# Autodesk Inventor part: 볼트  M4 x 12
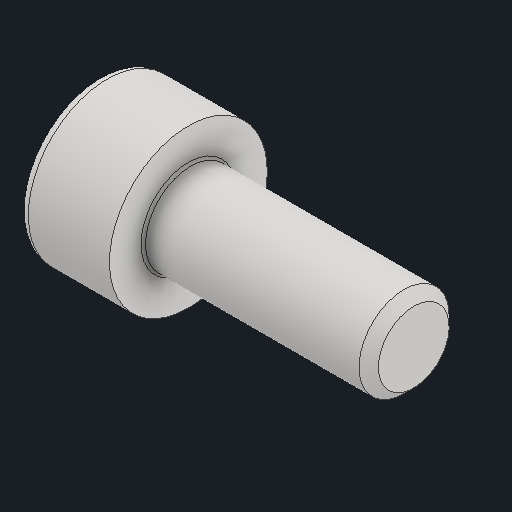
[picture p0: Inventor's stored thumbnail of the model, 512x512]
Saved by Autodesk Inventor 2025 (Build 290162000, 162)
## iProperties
Created: 2025-08
Part Number: 볼트  M4 x 12
Material: 스테인리스강
Description: 6각머리 태핑 나사
Document SubType Name: Modeling
Designer: infra14
Density: 8.08 g/cm^3
Appearance: 기본값
Author: jhkim
Sending System: Autodesk Inventor 2026
Preprocessor: ST-DEVELOPER v20.1
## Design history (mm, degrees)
feature "Solid1"
node "솔리드1"
